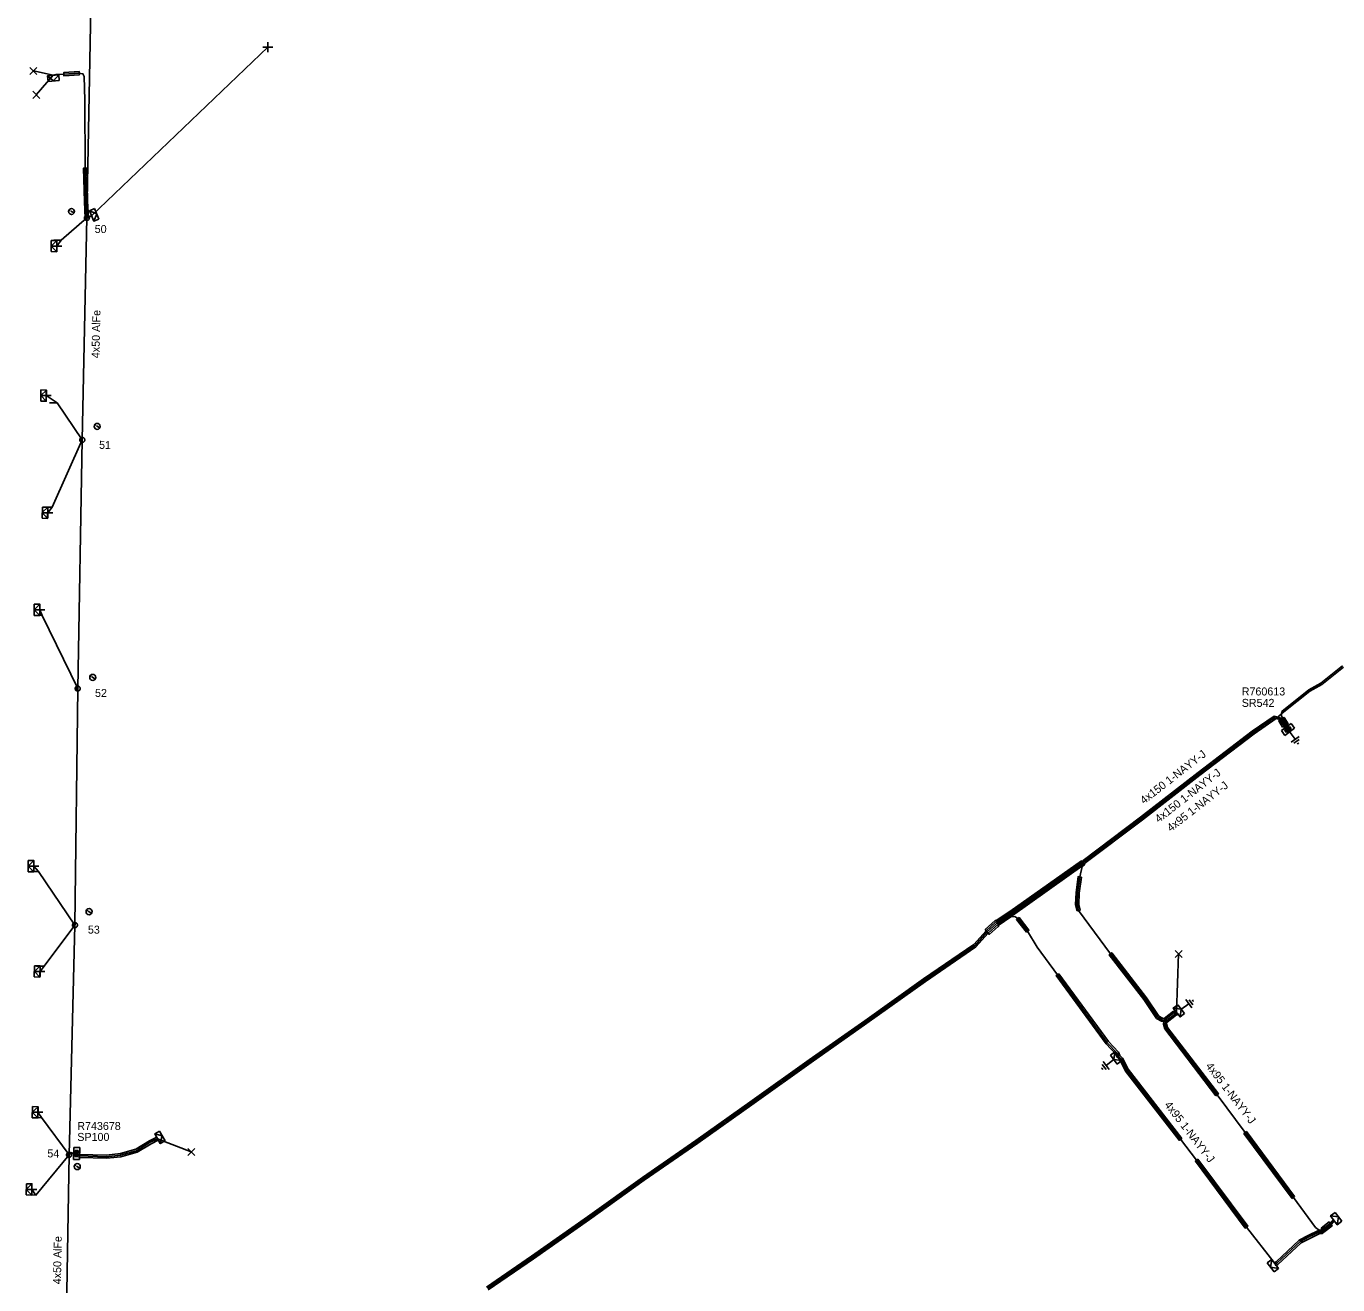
# Model space of a CAD drawing. Extents: x -544780 to -541582, y -1198995 to -1196551.
# Drawn here: x -543648 to -543484.1, y -1197316.4 to -1197159.1 of the extents above; entities that cross this region are included whole.
import ezdxf

# ---------------------------------------------------------------- set-up
doc = ezdxf.new("R2010")
doc.units = 0
for name, color, linetype in [('Vrstva 1', 7, 'Continuous'), ('Vrstva 10', 7, 'Continuous'), ('Vrstva 13', 7, 'Continuous'), ('Vrstva 14', 7, 'Continuous'), ('Vrstva 15', 7, 'Continuous'), ('Vrstva 2', 7, 'Continuous'), ('Vrstva 20', 7, 'Continuous'), ('Vrstva 28', 7, 'Continuous'), ('Vrstva 29', 7, 'Continuous'), ('Vrstva 30', 7, 'Continuous'), ('Vrstva 31', 7, 'Continuous'), ('Vrstva 34', 7, 'Continuous'), ('Vrstva 36', 7, 'Continuous'), ('Vrstva 5', 7, 'Continuous'), ('Vrstva 52', 7, 'Continuous'), ('Vrstva 54', 7, 'Continuous'), ('Vrstva 59', 7, 'Continuous'), ('Vrstva 6', 7, 'Continuous'), ('Vrstva 8', 7, 'Continuous'), ('Vrstva 9', 7, 'Continuous')]:
    doc.layers.add(name, color=color, linetype=linetype)

# ---------------------------------------------------------------- blocks, each defined once
blk = doc.blocks.new('NN440')
at = {"layer": 'Vrstva 2'}
for points in [[(0.63, 0), (0.63, 0.06), (0.62, 0.13), (0.6, 0.19), (0.58, 0.25), (0.55, 0.31), (0.51, 0.37), (0.47, 0.42), (0.42, 0.46), (0.37, 0.51), (0.32, 0.54), (0.26, 0.57), (0.2, 0.59), (0.13, 0.61), (0.07, 0.62), (0, 0.63), (-0.06, 0.62), (-0.13, 0.61), (-0.19, 0.59), (-0.26, 0.57), (-0.31, 0.54), (-0.37, 0.51), (-0.42, 0.46), (-0.47, 0.42), (-0.51, 0.37), (-0.54, 0.31), (-0.57, 0.25), (-0.6, 0.19), (-0.62, 0.13), (-0.63, 0.06), (-0.63, 0), (-0.63, -0.07), (-0.62, -0.14), (-0.6, -0.2), (-0.57, -0.26), (-0.54, -0.32), (-0.51, -0.37), (-0.47, -0.43), (-0.42, -0.47), (-0.37, -0.51), (-0.31, -0.55), (-0.26, -0.58), (-0.19, -0.6), (-0.13, -0.62), (-0.06, -0.63), (0, -0.63), (0.07, -0.63), (0.13, -0.62), (0.2, -0.6), (0.26, -0.58), (0.32, -0.55), (0.37, -0.51), (0.42, -0.47), (0.47, -0.43), (0.51, -0.37), (0.55, -0.32), (0.58, -0.26), (0.6, -0.2), (0.62, -0.14), (0.63, -0.07), (0.63, 0)], [(-0.63, 0), (0.63, 0)], [(-0.6, -0.18), (0.57, -0.18)], [(-0.51, -0.32), (0.5, -0.32)], [(-0.37, -0.47), (0.35, -0.47)]]:
    blk.add_lwpolyline(points, dxfattribs=at)
blk = doc.blocks.new('NN770')
at = {"layer": 'Vrstva 10'}
for p, q in [((0, 0.19), (0, 0.26)), ((0, -0.28), (0, 0.11))]:
    blk.add_line(p, q, dxfattribs=at)
blk.add_circle((0, -0.01), 0.375, dxfattribs=at)
blk = doc.blocks.new('NN800')
at = {"layer": 'Vrstva 1'}
for points in [[(-0.44, 0.44), (0.44, -0.44)], [(-0.44, -0.44), (0.44, 0.44)]]:
    blk.add_lwpolyline(points, dxfattribs=at)
blk = doc.blocks.new('NN620')
at = {"layer": 'Vrstva 8'}
for points in [[(0.75, 0), (-0.75, 0)], [(-0.75, 0), (-0.75, -0.75)], [(0.75, -0.75), (0.75, 0)], [(-0.75, -0.75), (0.75, -0.75)], [(0.37, -0.18), (-0.38, -0.18)], [(-0.38, -0.18), (-0.38, -0.56)], [(-0.38, -0.56), (0.37, -0.56)], [(0.32, -0.23), (-0.33, -0.23)], [(-0.33, -0.23), (-0.33, -0.51)], [(-0.33, -0.51), (0.32, -0.51)], [(0.27, -0.27), (-0.28, -0.27)], [(-0.28, -0.27), (-0.28, -0.46)], [(-0.28, -0.46), (0.27, -0.46)], [(0.23, -0.32), (-0.23, -0.32)], [(-0.23, -0.32), (-0.23, -0.42)], [(-0.23, -0.42), (0.23, -0.42)], [(-0.19, -0.37), (0.19, -0.37)], [(0.23, -0.42), (0.23, -0.32)], [(0.27, -0.46), (0.27, -0.27)], [(0.32, -0.51), (0.32, -0.23)], [(0.37, -0.56), (0.37, -0.18)]]:
    blk.add_lwpolyline(points, dxfattribs=at)
blk = doc.blocks.new('NN630')
at = {"layer": 'Vrstva 9'}
for points in [[(0, -0.7), (-0.7, 0)], [(-0.7, -0.7), (-0.7, 0), (0.7, 0), (0.7, -0.7)], [(-0.7, -0.7), (0.7, -0.7)], [(0, -0.7), (0.7, 0)]]:
    blk.add_lwpolyline(points, dxfattribs=at)
blk = doc.blocks.new('NN810')
at = {"layer": 'Vrstva 14'}
for points in [[(0, -0.64), (0, -1.89)], [(0.63, -1.89), (-0.62, -1.89)], [(0.39, -2.2), (-0.4, -2.2)], [(0, -2.52), (-0.12, -2.52)], [(0.14, -2.52), (0, -2.52)]]:
    blk.add_lwpolyline(points, dxfattribs=at)
blk = doc.blocks.new('NN510')
at = {"layer": 'Vrstva 2'}
blk.add_lwpolyline([(0, 0), (0, 0.94)], dxfattribs=at)

msp = doc.modelspace()

# ---------------------------------------------------------------- linework, layer by layer
at = {"layer": 'Vrstva 1'}
for points in [[(-543642.64, -1197300.18), (-543641.9, -1197271.48), (-543641.56, -1197241.91), (-543640.99, -1197210.83), (-543640.41, -1197183.09), (-543639.74, -1197148.04), (-543639.18, -1197116.19), (-543642.28, -1197095.84)], [(-543643.09, -1197327.06), (-543642.64, -1197300.18)]]:
    msp.add_lwpolyline(points, dxfattribs=at)
at = {"layer": 'Vrstva 20'}
for points in [[(-543641.35, -1197165.2), (-543643.29, -1197165.33), (-543643.31, -1197164.93), (-543641.37, -1197164.8)], [(-543640.43, -1197176.86), (-543640.33, -1197181.01), (-543640.22, -1197183.08), (-543640.62, -1197183.1), (-543640.73, -1197181.03), (-543640.83, -1197176.86)], [(-543490.96, -1197246.73), (-543491.45, -1197245.94), (-543490.77, -1197245.52), (-543490.28, -1197246.31)], [(-543526.75, -1197270.91), (-543525.07, -1197269.77), (-543516.1, -1197263.44), (-543515.76, -1197263.92), (-543524.73, -1197270.27), (-543526.41, -1197271.41)], [(-543516.12, -1197265.47), (-543516.38, -1197267.49), (-543516.78, -1197267.43), (-543516.52, -1197265.41)], [(-543516.65, -1197269.71), (-543516.85, -1197268.92), (-543516.78, -1197267.45), (-543516.38, -1197267.47), (-543516.45, -1197268.88), (-543516.27, -1197269.61)], [(-543528.16, -1197272.03), (-543526.89, -1197270.9), (-543526.59, -1197270.85), (-543526.46, -1197271.64), (-543526.53, -1197271.65), (-543527.62, -1197272.63)], [(-543522.99, -1197272.36), (-543524.23, -1197270.78), (-543523.91, -1197270.54), (-543522.67, -1197272.12)], [(-543505.52, -1197283.46), (-543505.66, -1197283.57), (-543506.1, -1197283.5), (-543506.72, -1197283.14), (-543508.3, -1197280.79), (-543512.64, -1197275.17), (-543512.32, -1197274.93), (-543507.98, -1197280.55), (-543506.44, -1197282.84), (-543505.96, -1197283.12), (-543505.77, -1197283.15)], [(-543518.95, -1197277.55), (-543512.73, -1197286.04), (-543511.48, -1197287.37), (-543511.32, -1197287.79), (-543511.7, -1197287.93), (-543511.82, -1197287.59), (-543513.03, -1197286.3), (-543519.27, -1197277.79)], [(-543505.77, -1197283.14), (-543504.61, -1197282.22), (-543504.23, -1197282.7), (-543505.39, -1197283.62)], [(-543504.5, -1197282.17), (-543504.29, -1197282.11), (-543504.13, -1197282.69), (-543504.34, -1197282.75)], [(-543499.31, -1197292.8), (-543505.7, -1197284.46), (-543505.86, -1197283.84), (-543505.79, -1197283.42), (-543505.64, -1197283.3), (-543505.39, -1197283.62), (-543505.42, -1197283.64), (-543505.46, -1197283.82), (-543505.34, -1197284.28), (-543498.99, -1197292.56)], [(-543511.37, -1197287.72), (-543510.99, -1197288.09), (-543510.25, -1197289.5), (-543503.58, -1197298.13), (-543503.9, -1197298.37), (-543510.59, -1197289.72), (-543511.31, -1197288.33), (-543511.65, -1197288)], [(-543489.78, -1197305.63), (-543495.81, -1197297.53), (-543495.49, -1197297.29), (-543489.46, -1197305.39)], [(-543631.5, -1197298.36), (-543632.39, -1197298.8), (-543634.13, -1197299.86), (-543636.15, -1197300.44), (-543637.93, -1197300.62), (-543641.39, -1197300.53), (-543641.37, -1197300.13), (-543637.95, -1197300.22), (-543636.23, -1197300.04), (-543634.29, -1197299.5), (-543632.59, -1197298.44), (-543631.68, -1197298)], [(-543501.55, -1197300.72), (-543495.31, -1197309.1), (-543495.63, -1197309.34), (-543501.87, -1197300.96)], [(-543486.16, -1197309.37), (-543485.15, -1197308.58), (-543484.79, -1197309.06), (-543485.8, -1197309.85)], [(-543491.98, -1197313.63), (-543491.79, -1197313.56), (-543488.88, -1197310.87), (-543487.76, -1197310.27), (-543486.41, -1197309.6), (-543486.14, -1197309.61), (-543486.04, -1197309.53), (-543485.8, -1197309.85), (-543486, -1197310.01), (-543486.32, -1197310), (-543487.58, -1197310.63), (-543488.64, -1197311.19), (-543491.57, -1197313.9), (-543491.82, -1197314.01)]]:
    msp.add_lwpolyline(points, close=True, dxfattribs=at)
at = {"layer": 'Vrstva 5'}
for points in [[(-543483.48, -1197239.07), (-543486.19, -1197241.24), (-543487.69, -1197242.06), (-543491.07, -1197244.79), (-543491.09, -1197245.06)], [(-543491.09, -1197245.06), (-543491.02, -1197245), (-543487.57, -1197242.22), (-543486.07, -1197241.4), (-543483.36, -1197239.23)], [(-543590.25, -1197317.07), (-543584.61, -1197313.18), (-543577.6, -1197308.26), (-543570.76, -1197303.36), (-543564.07, -1197298.71), (-543557.01, -1197293.72), (-543549.88, -1197288.64), (-543542.95, -1197283.75), (-543535.6, -1197278.53), (-543529.3, -1197274.2), (-543527.75, -1197272.47), (-543526.57, -1197271.42), (-543526.4, -1197271.43), (-543524.94, -1197270.43), (-543524.44, -1197270.39), (-543524.07, -1197270.66), (-543522.83, -1197272.24), (-543521.62, -1197274.22), (-543519.11, -1197277.67), (-543512.88, -1197286.17), (-543511.65, -1197287.48), (-543511.51, -1197287.86), (-543511.15, -1197288.21), (-543510.42, -1197289.61), (-543503.74, -1197298.25), (-543501.71, -1197300.84), (-543495.47, -1197309.22), (-543492.03, -1197313.63), (-543491.9, -1197313.82), (-543491.68, -1197313.73), (-543488.76, -1197311.03), (-543487.67, -1197310.45), (-543486.36, -1197309.8), (-543486.07, -1197309.81), (-543484.9, -1197308.89), (-543484.59, -1197308.55), (-543484.55, -1197308.36), (-543484.74, -1197308.42), (-543485.04, -1197308.75), (-543486.14, -1197309.61), (-543486.4, -1197309.6), (-543486.86, -1197309.26), (-543489.62, -1197305.51), (-543495.65, -1197297.41), (-543499.15, -1197292.68), (-543505.52, -1197284.37), (-543505.66, -1197283.83), (-543505.61, -1197283.53), (-543504.37, -1197282.55), (-543504.21, -1197282.4), (-543504.47, -1197282.37), (-543505.71, -1197283.36), (-543506.03, -1197283.31), (-543506.58, -1197282.99), (-543508.14, -1197280.67), (-543512.48, -1197275.05), (-543516.46, -1197269.66), (-543516.65, -1197268.9), (-543516.58, -1197267.46), (-543516.32, -1197265.44), (-543516.03, -1197264.15), (-543515.74, -1197263.94), (-543515.67, -1197263.74), (-543508.47, -1197258.32), (-543501.29, -1197252.74), (-543494.52, -1197247.56), (-543491.79, -1197245.65), (-543491.09, -1197245.06)], [(-543491.09, -1197245.06), (-543491.1, -1197245.37), (-543490.45, -1197246.42), (-543490.35, -1197246.6)], [(-543590.47, -1197316.74), (-543584.83, -1197312.86), (-543577.84, -1197307.94), (-543570.98, -1197303.04), (-543564.3, -1197298.39), (-543557.25, -1197293.4), (-543550.12, -1197288.32), (-543543.19, -1197283.43), (-543535.83, -1197278.21), (-543529.56, -1197273.9), (-543528.03, -1197272.19), (-543526.84, -1197271.12), (-543526.64, -1197271.08), (-543524.96, -1197269.94), (-543515.99, -1197263.6), (-543515.91, -1197263.42), (-543508.71, -1197258), (-543501.53, -1197252.42), (-543494.76, -1197247.24), (-543492.04, -1197245.34), (-543491.19, -1197245.6), (-543490.62, -1197246.52), (-543490.51, -1197246.72)], [(-543590.36, -1197316.9), (-543584.72, -1197313.02), (-543577.72, -1197308.1), (-543570.87, -1197303.2), (-543564.18, -1197298.55), (-543557.13, -1197293.56), (-543550, -1197288.48), (-543543.07, -1197283.59), (-543535.72, -1197278.37), (-543529.43, -1197274.05), (-543527.89, -1197272.33), (-543526.71, -1197271.27), (-543526.52, -1197271.24), (-543524.84, -1197270.1), (-543515.87, -1197263.76), (-543515.79, -1197263.58), (-543508.59, -1197258.16), (-543501.41, -1197252.58), (-543494.64, -1197247.4), (-543492.01, -1197245.56), (-543491.32, -1197245.77), (-543490.79, -1197246.62), (-543490.67, -1197246.84)], [(-543642.64, -1197300.18), (-543642.43, -1197299.91), (-543642.07, -1197300.01)]]:
    msp.add_lwpolyline(points, dxfattribs=at)
at = {"layer": 'Vrstva 52'}
for points in [[(-543640.42, -1197183.09), (-543640.53, -1197181.02), (-543640.63, -1197176.86), (-543640.66, -1197168.38), (-543640.75, -1197165.41), (-543640.91, -1197165.07), (-543641.36, -1197165), (-543643.3, -1197165.13), (-543644.28, -1197165.14), (-543644.63, -1197165.26)], [(-543641.38, -1197300.33), (-543637.94, -1197300.42), (-543636.19, -1197300.24), (-543634.21, -1197299.68), (-543632.49, -1197298.62), (-543631.59, -1197298.18)]]:
    msp.add_lwpolyline(points, dxfattribs=at)
at = {"layer": 'Vrstva 54'}
for points in [[(-543640.41, -1197183.09), (-543643.61, -1197185.88), (-543644.17, -1197186.61)], [(-543640.41, -1197183.09), (-543639.83, -1197182.84)], [(-543640.99, -1197210.83), (-543644.14, -1197206.19), (-543645.48, -1197205.3)], [(-543640.99, -1197210.83), (-543644.77, -1197219.25), (-543645.3, -1197219.94)], [(-543641.56, -1197241.91), (-543646.02, -1197232.76), (-543646.29, -1197232.07)], [(-543641.9, -1197271.48), (-543646.46, -1197264.79), (-543647.05, -1197264.11)], [(-543642.64, -1197300.18), (-543646.1, -1197295.54), (-543646.53, -1197294.87)], [(-543642.64, -1197300.18), (-543646.81, -1197305.21), (-543647.28, -1197304.51)]]:
    msp.add_lwpolyline(points, dxfattribs=at)
at = {"layer": 'Vrstva 59'}
for points in [[(-543639.83, -1197182.84), (-543617.81, -1197161.76)], [(-543644.63, -1197165.26), (-543647.1, -1197164.72)], [(-543644.63, -1197165.26), (-543646.74, -1197167.7)], [(-543504.21, -1197282.4), (-543503.97, -1197275.07)], [(-543631.59, -1197298.18), (-543627.36, -1197299.83)]]:
    msp.add_lwpolyline(points, dxfattribs=at)
at = {"layer": 'Vrstva 8'}
msp.add_lwpolyline([(-543641.9, -1197271.48), (-543645.75, -1197276.6), (-543646.27, -1197277.27)], dxfattribs=at)

# ---------------------------------------------------------------- block references
at = {"layer": 'Vrstva 13'}
for p, xscale, yscale, rotation in [((-543640.41, -1197183.09), 0.49999999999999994, 0.5000000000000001, -90.8369305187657), ((-543640.99, -1197210.83), 0.5, 0.5000000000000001, -91.71788889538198), ((-543641.56, -1197241.91), 0.5, 0.49999999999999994, -90.74085274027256), ((-543641.9, -1197271.48), 0.5, 0.5, -90.83333329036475), ((-543642.64, -1197300.18), 0.5, 0.5000000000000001, -91.20351667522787)]:
    msp.add_blockref('NN440', p, dxfattribs=dict(at, xscale=xscale, yscale=yscale, rotation=rotation))
for p, rotation in [((-543643.61, -1197185.88), 88.92716942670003), ((-543644.14, -1197206.19), 89.44997772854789), ((-543644.77, -1197219.25), 88.31861116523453), ((-543646.02, -1197232.76), 89.31996391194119), ((-543646.46, -1197264.79), 89.09872496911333), ((-543645.75, -1197276.6), 89.21967498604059), ((-543646.1, -1197295.55), 89.09421388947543), ((-543646.73, -1197305.21), 89.31963050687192)]:
    msp.add_blockref('NN510', p, dxfattribs=dict(at, rotation=rotation))
at = {"layer": 'Vrstva 15'}
for p, rotation in [((-543490.51, -1197246.72), 35.77711299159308), ((-543504.21, -1197282.4), 125.75234685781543), ((-543511.51, -1197287.86), -52.456904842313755)]:
    msp.add_blockref('NN810', p, dxfattribs=dict(at, rotation=rotation))
at = {"layer": 'Vrstva 28'}
for p, rotation in [((-543490.51, -1197246.72), 36.38435319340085), ((-543642.07, -1197300.01), 87.82480075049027)]:
    msp.add_blockref('NN620', p, dxfattribs=dict(at, rotation=rotation))
at = {"layer": 'Vrstva 31'}
for p, rotation in [((-543644.63, -1197165.26), 5.09211513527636), ((-543639.83, -1197182.84), 112.38548055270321), ((-543644.17, -1197186.61), -91.0728305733), ((-543645.48, -1197205.3), -90.57398338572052), ((-543645.3, -1197219.94), -91.6813888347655), ((-543646.29, -1197232.07), -90.68003615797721), ((-543647.05, -1197264.11), -90.90127502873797), ((-543646.27, -1197277.27), -90.78032501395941), ((-543504.21, -1197282.4), 127.17447939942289), ((-543511.51, -1197287.86), -52.81900925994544), ((-543646.53, -1197294.87), -90.90578617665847), ((-543631.59, -1197298.18), 119.74488133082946), ((-543647.28, -1197304.51), -90.68036949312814), ((-543484.55, -1197308.36), 127.11108553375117), ((-543491.9, -1197313.82), -52.94238019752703)]:
    msp.add_blockref('NN630', p, dxfattribs=dict(at, rotation=rotation))
at = {"layer": 'Vrstva 34'}
for p, rotation in [((-543617.81, -1197161.76), 45), ((-543644.17, -1197186.61), 45), ((-543645.48, -1197205.3), 45.00000009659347), ((-543645.3, -1197219.94), 45), ((-543646.29, -1197232.07), 45), ((-543647.05, -1197264.11), 45), ((-543646.27, -1197277.27), 45), ((-543646.53, -1197294.87), 45), ((-543647.28, -1197304.51), 45)]:
    msp.add_blockref('NN800', p, dxfattribs=dict(at, rotation=rotation))
for p in [(-543647.1, -1197164.72), (-543646.74, -1197167.7), (-543503.97, -1197275.07), (-543627.36, -1197299.83)]:
    msp.add_blockref('NN800', p, dxfattribs=at)
at = {"layer": 'Vrstva 36', "rotation": 58.516302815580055}
for p in [(-543642.34, -1197182.28), (-543639.13, -1197209.14), (-543639.69, -1197240.51), (-543640.15, -1197269.79), (-543641.62, -1197301.65)]:
    msp.add_blockref('NN770', p, dxfattribs=at)

# ---------------------------------------------------------------- texts
at = {"layer": 'Vrstva 14'}
for s, rotation, p in [('50', 359.163, (-543639.44, -1197184.96)), ('51', 358.282, (-543638.9, -1197211.94)), ('52', 359.259, (-543639.4, -1197242.95)), ('53', 359.167, (-543640.29, -1197272.53)), ('54', 358.796, (-543645.36, -1197300.5))]:
    msp.add_text(s, height=1, rotation=rotation, dxfattribs=at).set_placement(p)
at = {"layer": 'Vrstva 2'}
for rotation, p in [(88.798, (-543638.84, -1197200.62)), (89.041, (-543643.65, -1197316.37))]:
    msp.add_text('4x50 AlFe', height=1, rotation=rotation, dxfattribs=at).set_placement(p)
at = {"layer": 'Vrstva 29'}
for s, p in [('R760613', (-543496.07, -1197242.77)), ('R743678', (-543641.61, -1197297.08))]:
    msp.add_text(s, height=1, dxfattribs=at).set_placement(p)
at = {"layer": 'Vrstva 30'}
for s, p in [('SR542', (-543496.07, -1197244.2)), ('SP100', (-543641.61, -1197298.45))]:
    msp.add_text(s, height=1, dxfattribs=at).set_placement(p)
at = {"layer": 'Vrstva 6'}
for s, rotation, p in [('4x150 1-NAYY-J', 37.852, (-543508.29, -1197256.41)), ('4x150 1-NAYY-J', 37.853, (-543506.45, -1197258.73)), ('4x95 1-NAYY-J', 37.854, (-543504.94, -1197259.86)), ('4x95 1-NAYY-J', 307.472, (-543500.63, -1197289.11)), ('4x95 1-NAYY-J', 307.709, (-543505.79, -1197293.97))]:
    msp.add_text(s, height=1, rotation=rotation, dxfattribs=at).set_placement(p)

doc.saveas('drawing.dxf')
